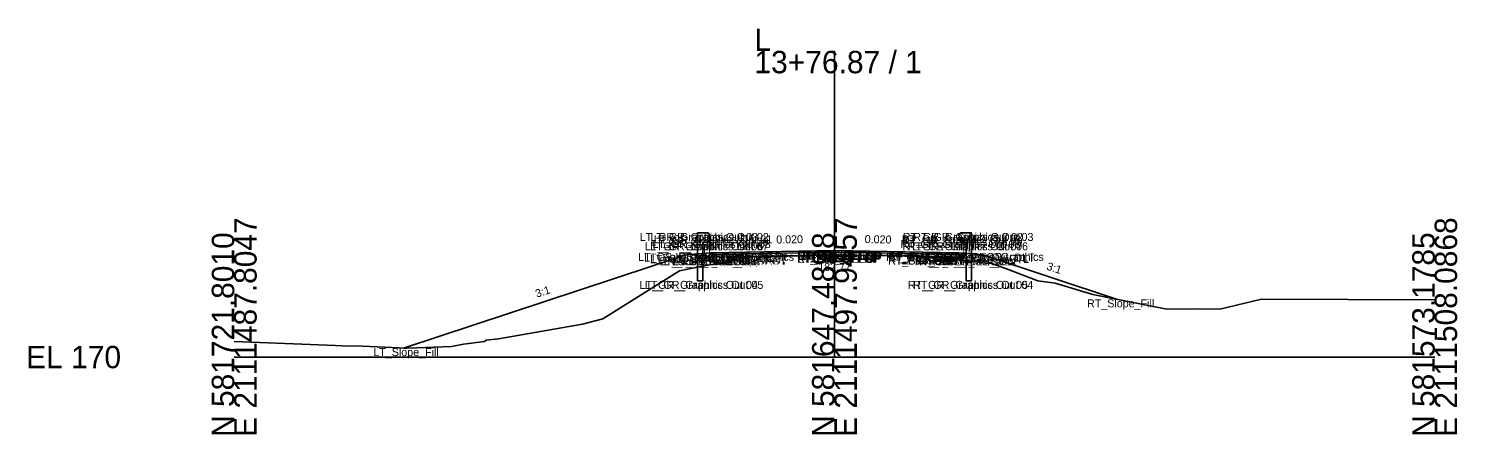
# Model space of a CAD drawing. Extents: x -486 to 1153, y -333 to 9539.
# Drawn here: x -25.7 to 152.8, y 3490.3 to 3541.1 of the extents above; entities that cross this region are included whole.
import ezdxf

# ---------------------------------------------------------------- set-up
doc = ezdxf.new("R2010")
doc.units = 0
for name, color, linetype in [('Default', 7, 'Continuous'), ('Exist Cross Section Cell', 7, 'Continuous'), ('Exist XS Ground Line', 7, 'Continuous'), ('Prop CMT Guardrail Graphics', 7, 'Continuous'), ('Prop CMT Pvmt Course 1', 7, 'Continuous'), ('Prop CMT Pvmt Course 2', 7, 'Continuous'), ('Prop CMT Pvmt Course 3', 7, 'Continuous'), ('Prop CMT Pvmt Surface', 7, 'Continuous'), ('Prop CMT Pvmt Surface Shoulder', 7, 'Continuous'), ('Prop CMT Shld Paved Course 1', 7, 'Continuous'), ('Prop CMT Shld Paved Course 2', 7, 'Continuous'), ('Prop CMT Shld Paved Course 3', 7, 'Continuous'), ('Prop CMT Slope Grass', 7, 'Continuous'), ('Prop CMT Subgrade Earthwork', 7, 'Continuous'), ('Prop XS Earthwork Shape', 7, 'Continuous'), ('Prop XS SE Text', 7, 'Continuous'), ('Prop XS Side Slope Text', 7, 'Continuous'), ('Scratch_Level_0', 7, 'Continuous')]:
    doc.layers.add(name, color=color, linetype=linetype)

msp = doc.modelspace()

# ---------------------------------------------------------------- linework, layer by layer
at = {"layer": 'Exist Cross Section Cell'}
for p, q in [((75, 3500), (75, 3538.32)), ((0, 3500), (75, 3500)), ((75, 3500), (150, 3500))]:
    msp.add_line(p, q, dxfattribs=at)
at = {"layer": 'Exist XS Ground Line'}
for p, q in [((56.83, 3511.02), (64.1, 3512.45)), ((64.1, 3512.45), (64.49, 3512.48)), ((64.49, 3512.48), (73.86, 3512.76)), ((73.86, 3512.76), (74.21, 3512.77)), ((74.21, 3512.77), (75, 3512.77)), ((75, 3512.77), (83.8, 3512.71)), ((83.8, 3512.71), (84.19, 3512.71)), ((84.19, 3512.71), (85.28, 3512.72)), ((85.28, 3512.72), (93.13, 3511.93)), ((93.13, 3511.93), (94.2, 3511.86)), ((94.2, 3511.86), (96.82, 3510.91)), ((46.06, 3504.78), (55.65, 3510.8)), ((55.65, 3510.8), (56.83, 3511.02)), ((96.82, 3510.91), (100.4, 3509.54)), ((100.4, 3509.54), (102.59, 3509.23)), ((102.59, 3509.23), (107.29, 3507.83)), ((107.29, 3507.83), (116.53, 3506.01)), ((123.15, 3505.98), (128.38, 3507.24)), ((128.38, 3507.24), (150, 3507.18)), ((43.5, 3504.1), (46.06, 3504.78)), ((116.53, 3506.01), (119.81, 3506.04)), ((119.81, 3506.04), (123.15, 3505.98)), ((33.04, 3502.29), (43.5, 3504.1)), ((0, 3501.95), (8.43, 3501.59)), ((8.43, 3501.59), (12.64, 3501.44)), ((12.64, 3501.44), (13.49, 3501.42)), ((13.49, 3501.42), (16.01, 3501.36)), ((16.01, 3501.36), (21.51, 3501.1)), ((21.51, 3501.1), (22.81, 3501.16)), ((22.81, 3501.16), (27.14, 3501.32)), ((27.14, 3501.32), (28.67, 3501.59)), ((28.67, 3501.59), (31.26, 3501.96)), ((31.26, 3501.96), (31.47, 3502.12)), ((31.47, 3502.12), (33.04, 3502.29))]:
    msp.add_line(p, q, dxfattribs=at)
at = {"layer": 'Prop CMT Guardrail Graphics'}
for points in [[(57.88, 3509.53), (57.88, 3515.53)], [(57.88, 3515.53), (59.21, 3515.53), (59.48, 3515.23)], [(92.12, 3515.53), (90.79, 3515.53), (90.52, 3515.23)], [(92.12, 3509.53), (92.12, 3515.53)], [(59.48, 3514.65), (59.21, 3514.36), (58.55, 3514.36)], [(58.55, 3514.36), (58.55, 3509.53)], [(59.48, 3515.23), (59.21, 3514.94)], [(59.21, 3514.94), (59.48, 3514.65)], [(90.52, 3515.23), (90.79, 3514.94)], [(90.79, 3514.94), (90.52, 3514.65)], [(90.52, 3514.65), (90.79, 3514.36), (91.45, 3514.36)], [(91.45, 3514.36), (91.45, 3509.53)], [(58.55, 3509.53), (57.88, 3509.53)], [(91.45, 3509.53), (92.12, 3509.53)]]:
    msp.add_lwpolyline(points, dxfattribs=at)
at = {"layer": 'Prop CMT Pvmt Course 1'}
for points in [[(75, 3513.34), (64, 3513.12)], [(64, 3512.91), (75, 3513.13)], [(64, 3513.12), (64, 3512.91)], [(75, 3513.13), (75, 3513.34)], [(75, 3513.34), (86, 3513.12)], [(75, 3513.13), (75, 3513.34)], [(86, 3512.91), (75, 3513.13)], [(86, 3513.12), (86, 3512.91)]]:
    msp.add_lwpolyline(points, dxfattribs=at)
msp.add_lwpolyline([(75, 3513.13), (75, 3513.22), (75, 3513.22), (75, 3513.13)], close=True, dxfattribs=at)
msp.add_lwpolyline([(75, 3513.13), (75, 3513.22), (75, 3513.22), (75, 3513.13)], close=True, dxfattribs=at)
at = {"layer": 'Prop CMT Pvmt Course 2'}
for points in [[(75, 3513.13), (64, 3512.91)], [(64, 3512.91), (64, 3512.58)], [(64, 3512.58), (75, 3512.8)], [(75, 3512.8), (75, 3513.13)], [(75, 3512.8), (75, 3513.13)], [(75, 3513.13), (86, 3512.91)], [(86, 3512.58), (75, 3512.8)], [(86, 3512.91), (86, 3512.58)]]:
    msp.add_lwpolyline(points, dxfattribs=at)
at = {"layer": 'Prop CMT Pvmt Course 3'}
for points in [[(75, 3512.8), (64, 3512.58)], [(64, 3512.58), (64, 3512.58)], [(75, 3512.8), (75, 3512.8)], [(75, 3512.8), (86, 3512.58)], [(75, 3512.8), (75, 3512.8)], [(86, 3512.58), (86, 3512.58)]]:
    msp.add_lwpolyline(points, dxfattribs=at)
at = {"layer": 'Prop CMT Pvmt Surface'}
for points in [[(75, 3513.34), (64, 3513.12)], [(75, 3513.34), (86, 3513.12)]]:
    msp.add_lwpolyline(points, dxfattribs=at)
at = {"layer": 'Prop CMT Pvmt Surface Shoulder'}
for points in [[(64, 3513.12), (59.58, 3513.03)], [(86, 3513.12), (90.42, 3513.03)]]:
    msp.add_lwpolyline(points, dxfattribs=at)
at = {"layer": 'Prop CMT Shld Paved Course 1'}
for points in [[(64, 3513.12), (59.58, 3513.03), (59.37, 3512.82)], [(59.37, 3512.82), (64, 3512.91)], [(64, 3512.91), (64, 3513.12)], [(86, 3513.12), (90.42, 3513.03), (90.63, 3512.82)], [(86, 3512.91), (86, 3513.12)], [(90.63, 3512.82), (86, 3512.91)]]:
    msp.add_lwpolyline(points, dxfattribs=at)
at = {"layer": 'Prop CMT Shld Paved Course 2'}
for points in [[(64, 3512.91), (59.37, 3512.82), (59.03, 3512.48)], [(59.03, 3512.48), (64, 3512.58)], [(64, 3512.58), (64, 3512.91)], [(86, 3512.91), (90.63, 3512.82), (90.97, 3512.48)], [(86, 3512.58), (86, 3512.91)], [(90.97, 3512.48), (86, 3512.58)]]:
    msp.add_lwpolyline(points, dxfattribs=at)
at = {"layer": 'Prop CMT Shld Paved Course 3'}
for points in [[(64, 3512.58), (59.03, 3512.48)], [(59.03, 3512.48), (59.03, 3512.48), (59.03, 3512.48)], [(64, 3512.58), (64, 3512.58)], [(86, 3512.58), (90.97, 3512.48)], [(86, 3512.58), (86, 3512.58)], [(90.97, 3512.48), (90.97, 3512.48), (90.97, 3512.48)]]:
    msp.add_lwpolyline(points, dxfattribs=at)
at = {"layer": 'Prop CMT Slope Grass'}
for points in [[(56.48, 3512.79), (21.14, 3501.12)], [(59.48, 3513.03), (56.48, 3512.79)], [(59.58, 3513.03), (59.48, 3513.03)], [(90.42, 3513.03), (90.52, 3513.03)], [(90.52, 3513.03), (93.52, 3512.79)], [(93.52, 3512.79), (110.38, 3507.22)]]:
    msp.add_lwpolyline(points, dxfattribs=at)
at = {"layer": 'Prop CMT Subgrade Earthwork'}
for points in [[(59.03, 3512.48), (58.56, 3512.95)], [(64, 3512.58), (59.03, 3512.48)], [(75, 3512.8), (64, 3512.58)], [(75, 3512.8), (86, 3512.58)], [(86, 3512.58), (90.97, 3512.48)], [(90.97, 3512.48), (91.44, 3512.95)]]:
    msp.add_lwpolyline(points, dxfattribs=at)
at = {"layer": 'Prop XS Earthwork Shape'}
for points in [[(58.56, 3512.95), (56.48, 3512.79), (21.14, 3501.12), (21.51, 3501.1), (22.81, 3501.16), (27.14, 3501.32), (28.67, 3501.59), (31.26, 3501.96), (31.47, 3502.12), (33.04, 3502.29), (43.5, 3504.1), (46.06, 3504.78), (55.65, 3510.8), (56.83, 3511.02), (64.1, 3512.45), (64.49, 3512.48), (73.86, 3512.76), (74.21, 3512.77), (75, 3512.77), (77.43, 3512.75), (75, 3512.8), (64, 3512.58), (59.03, 3512.48)], [(77.43, 3512.75), (83.8, 3512.71), (84.19, 3512.71), (85.28, 3512.72), (86.79, 3512.56), (86, 3512.58)], [(96.82, 3510.91), (100.4, 3509.54), (102.59, 3509.23), (107.29, 3507.83), (110.38, 3507.22), (93.52, 3512.79), (91.44, 3512.95), (90.97, 3512.48), (86.79, 3512.56), (93.13, 3511.93), (94.2, 3511.86)]]:
    msp.add_lwpolyline(points, close=True, dxfattribs=at)

# ---------------------------------------------------------------- texts
at = {"layer": 'Default'}
for s, height, p in [('182.77', 1, (72.97, 3510.77)), ('-', 0.0001, (0, 3500))]:
    msp.add_text(s, height=height, dxfattribs=at).set_placement(p)
at = {"layer": 'Exist Cross Section Cell'}
for s, p in [('L', (65, 3538.32)), ('13+76.87 / 1', (65, 3535.52)), ('EL 170', (-26, 3498.6))]:
    msp.add_text(s, height=2.8, dxfattribs=at).set_placement(p)
for s, p in [('E 2111487.8047', (2.8, 3490)), ('E 2111497.9457', (77.8, 3490)), ('E 2111508.0868', (152.8, 3490)), ('N 581721.8010', (0, 3490)), ('N 581647.4898', (75, 3490)), ('N 581573.1785', (150, 3490))]:
    msp.add_text(s, height=2.8, rotation=90, dxfattribs=at).set_placement(p)
at = {"layer": 'Prop XS SE Text'}
for rotation, p in [(1.1458, (67.73, 3514.2)), (358.8542, (78.77, 3514.27))]:
    msp.add_text('0.020', height=1, rotation=rotation, dxfattribs=at).set_placement(p)
at = {"layer": 'Prop XS Side Slope Text'}
for rotation, p in [(341.7371, (101.43, 3510.96)), (18.2629, (37.82, 3507.42))]:
    msp.add_text('3:1', height=1, rotation=rotation, dxfattribs=at).set_placement(p)
at = {"layer": 'Scratch_Level_0'}
for s, p in [('LT_GR_Graphics Out 03', (50.66, 3514.53)), ('LT_GR_Graphics Out 02', (52.01, 3514.53)), ('RT_GR_Graphics Out 02', (83.53, 3514.53)), ('RT_GR_Graphics Out 03', (84.85, 3514.53)), ('LT_GR_Graphics Out 06', (51.32, 3513.36)), ('LT_GR_Graphics Out 07', (51.97, 3513.36)), ('LT_GR_Graphics Out 09', (51.99, 3513.94)), ('LT_GR_Graphics Out 08', (52.25, 3513.65)), ('LT_GR_Graphics Out 01', (52.43, 3514.23)), ('RT_GR_Graphics Out 08', (83.23, 3513.65)), ('RT_GR_Graphics Out 01', (83.4, 3514.23)), ('RT_GR_Graphics Out 07', (83.49, 3513.36)), ('RT_GR_Graphics Out 09', (83.5, 3513.94)), ('RT_GR_Graphics Out 06', (84.17, 3513.36)), ('LT_GS_OS_GR_Face_Graphics', (50.48, 3512.03)), ('LT_Sub_Trench_Out_DLT', (51.21, 3511.95)), ('LT_GS_OS_CTL', (51.95, 3511.79)), ('LT_Sub_Trench_Out', (53.14, 3511.48)), ('LT_PS3_Shelf_Out', (53.69, 3511.48)), ('LT_PS3_OEOP', (54.82, 3511.48)), ('LT_PS2_OEOP', (55.16, 3511.82)), ('LT_PS1_OEOP', (55.49, 3512.03)), ('LT_PV2_OEOT', (59.75, 3511.91)), ('LT_PV3_OEOT', (59.75, 3511.58)), ('LT_Sub_OEOT', (59.77, 3511.58)), ('LT_PV1_OEOT', (59.87, 3512.12)), ('RT_PV2_OEEOP', (70.33, 3512.13)), ('RT_PV3_OEEOP', (70.33, 3511.8)), ('RT_Sub_OEEOP', (70.36, 3511.8)), ('LT_PV2_OEEOP', (70.39, 3512.13)), ('LT_PV3_OEEOP', (70.39, 3511.8)), ('LT_Sub_OEEOP', (70.42, 3511.8)), ('RT_PV1_OEEOP', (70.45, 3512.22)), ('LT_PV1_OEEOP', (70.51, 3512.22)), ('RT_PV2_IEEOP', (70.71, 3512.13)), ('LT_PV2_IEEOP', (70.77, 3512.13)), ('RT_PV1_IEEOP', (70.83, 3512.22)), ('LT_PV1_IEEOP', (70.89, 3512.22)), ('PV2_PGL', (72.35, 3512.13)), ('PV1_PGL', (72.47, 3512.34)), ('RT_GS_OS_GR_Face_Graphics', (81.45, 3512.03)), ('RT_PV2_OEOT', (81.69, 3511.91)), ('RT_PV3_OEOT', (81.69, 3511.58)), ('RT_Sub_OEOT', (81.71, 3511.58)), ('RT_PV1_OEOT', (81.81, 3512.12)), ('RT_Sub_Trench_Out_DLT', (84.03, 3511.95)), ('RT_Sub_Trench_Out', (85.02, 3511.48)), ('RT_PS3_Shelf_Out', (85.57, 3511.48)), ('RT_PS1_OEOP', (86.26, 3512.03)), ('RT_PS2_OEOP', (86.36, 3511.82)), ('RT_PS3_OEOP', (86.7, 3511.48)), ('RT_GS_OS_CTL', (88.92, 3511.79)), ('LT_GR_Graphics Out 04', (50.65, 3508.53)), ('LT_GR_Graphics Out 05', (51.32, 3508.53)), ('RT_GR_Graphics Out 05', (84.17, 3508.53)), ('RT_GR_Graphics Out 04', (84.83, 3508.53)), ('RT_Slope_Fill', (106.56, 3506.22)), ('LT_Slope_Fill', (17.38, 3500.12))]:
    msp.add_text(s, height=1, dxfattribs=at).set_placement(p)

doc.saveas('drawing.dxf')
